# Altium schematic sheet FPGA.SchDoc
size A0
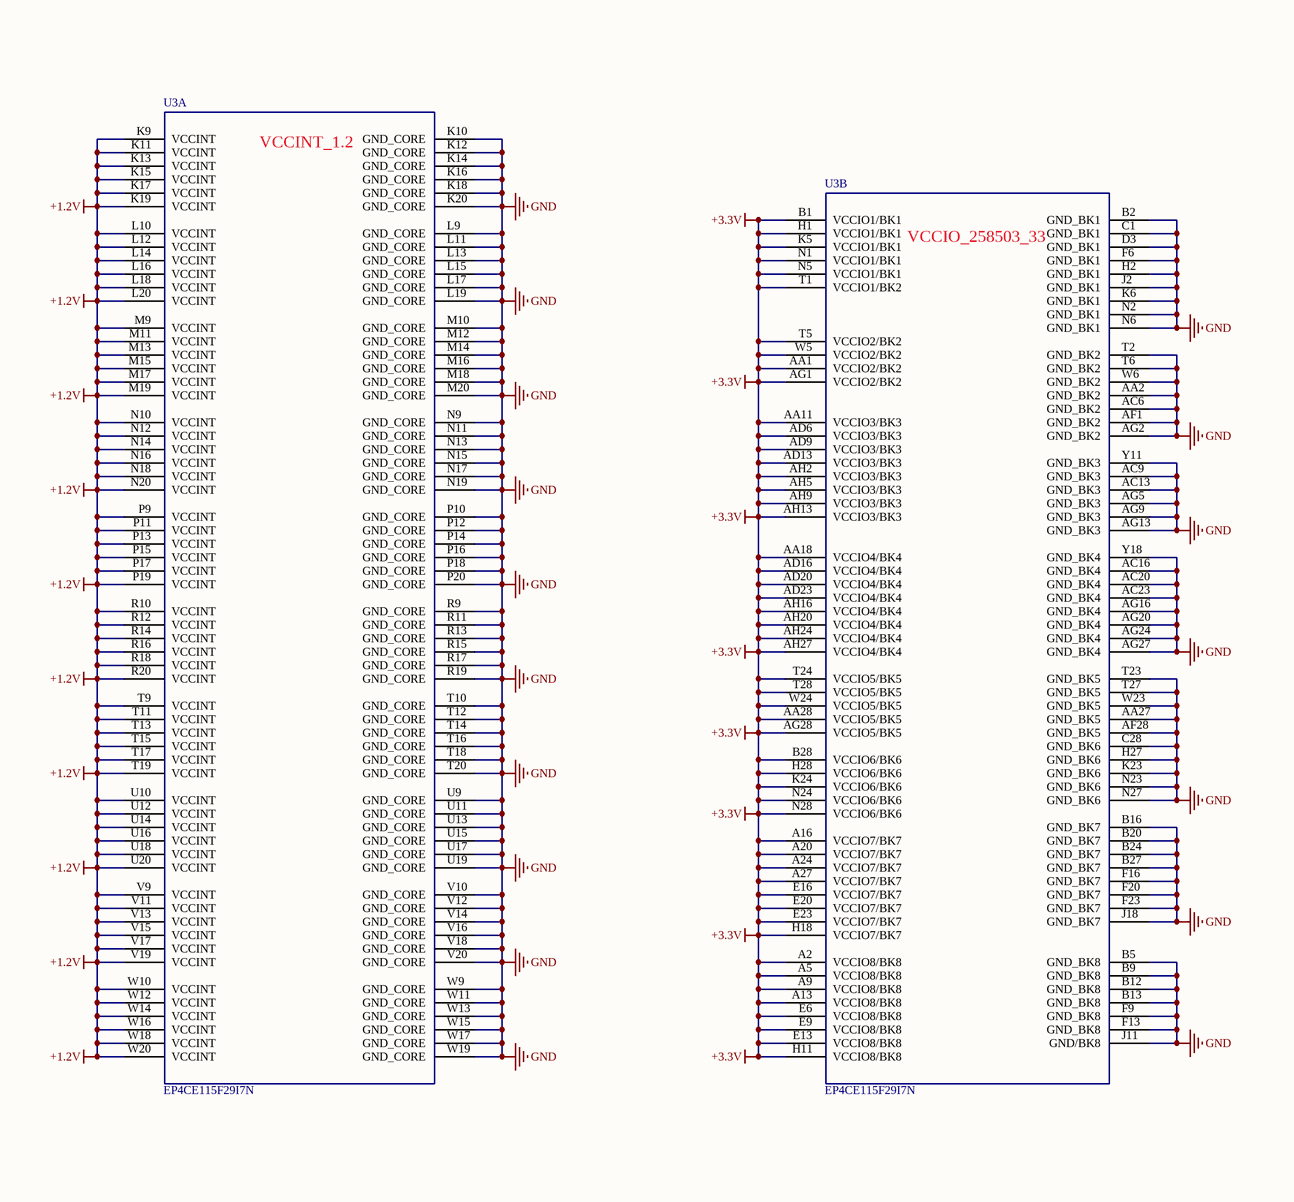
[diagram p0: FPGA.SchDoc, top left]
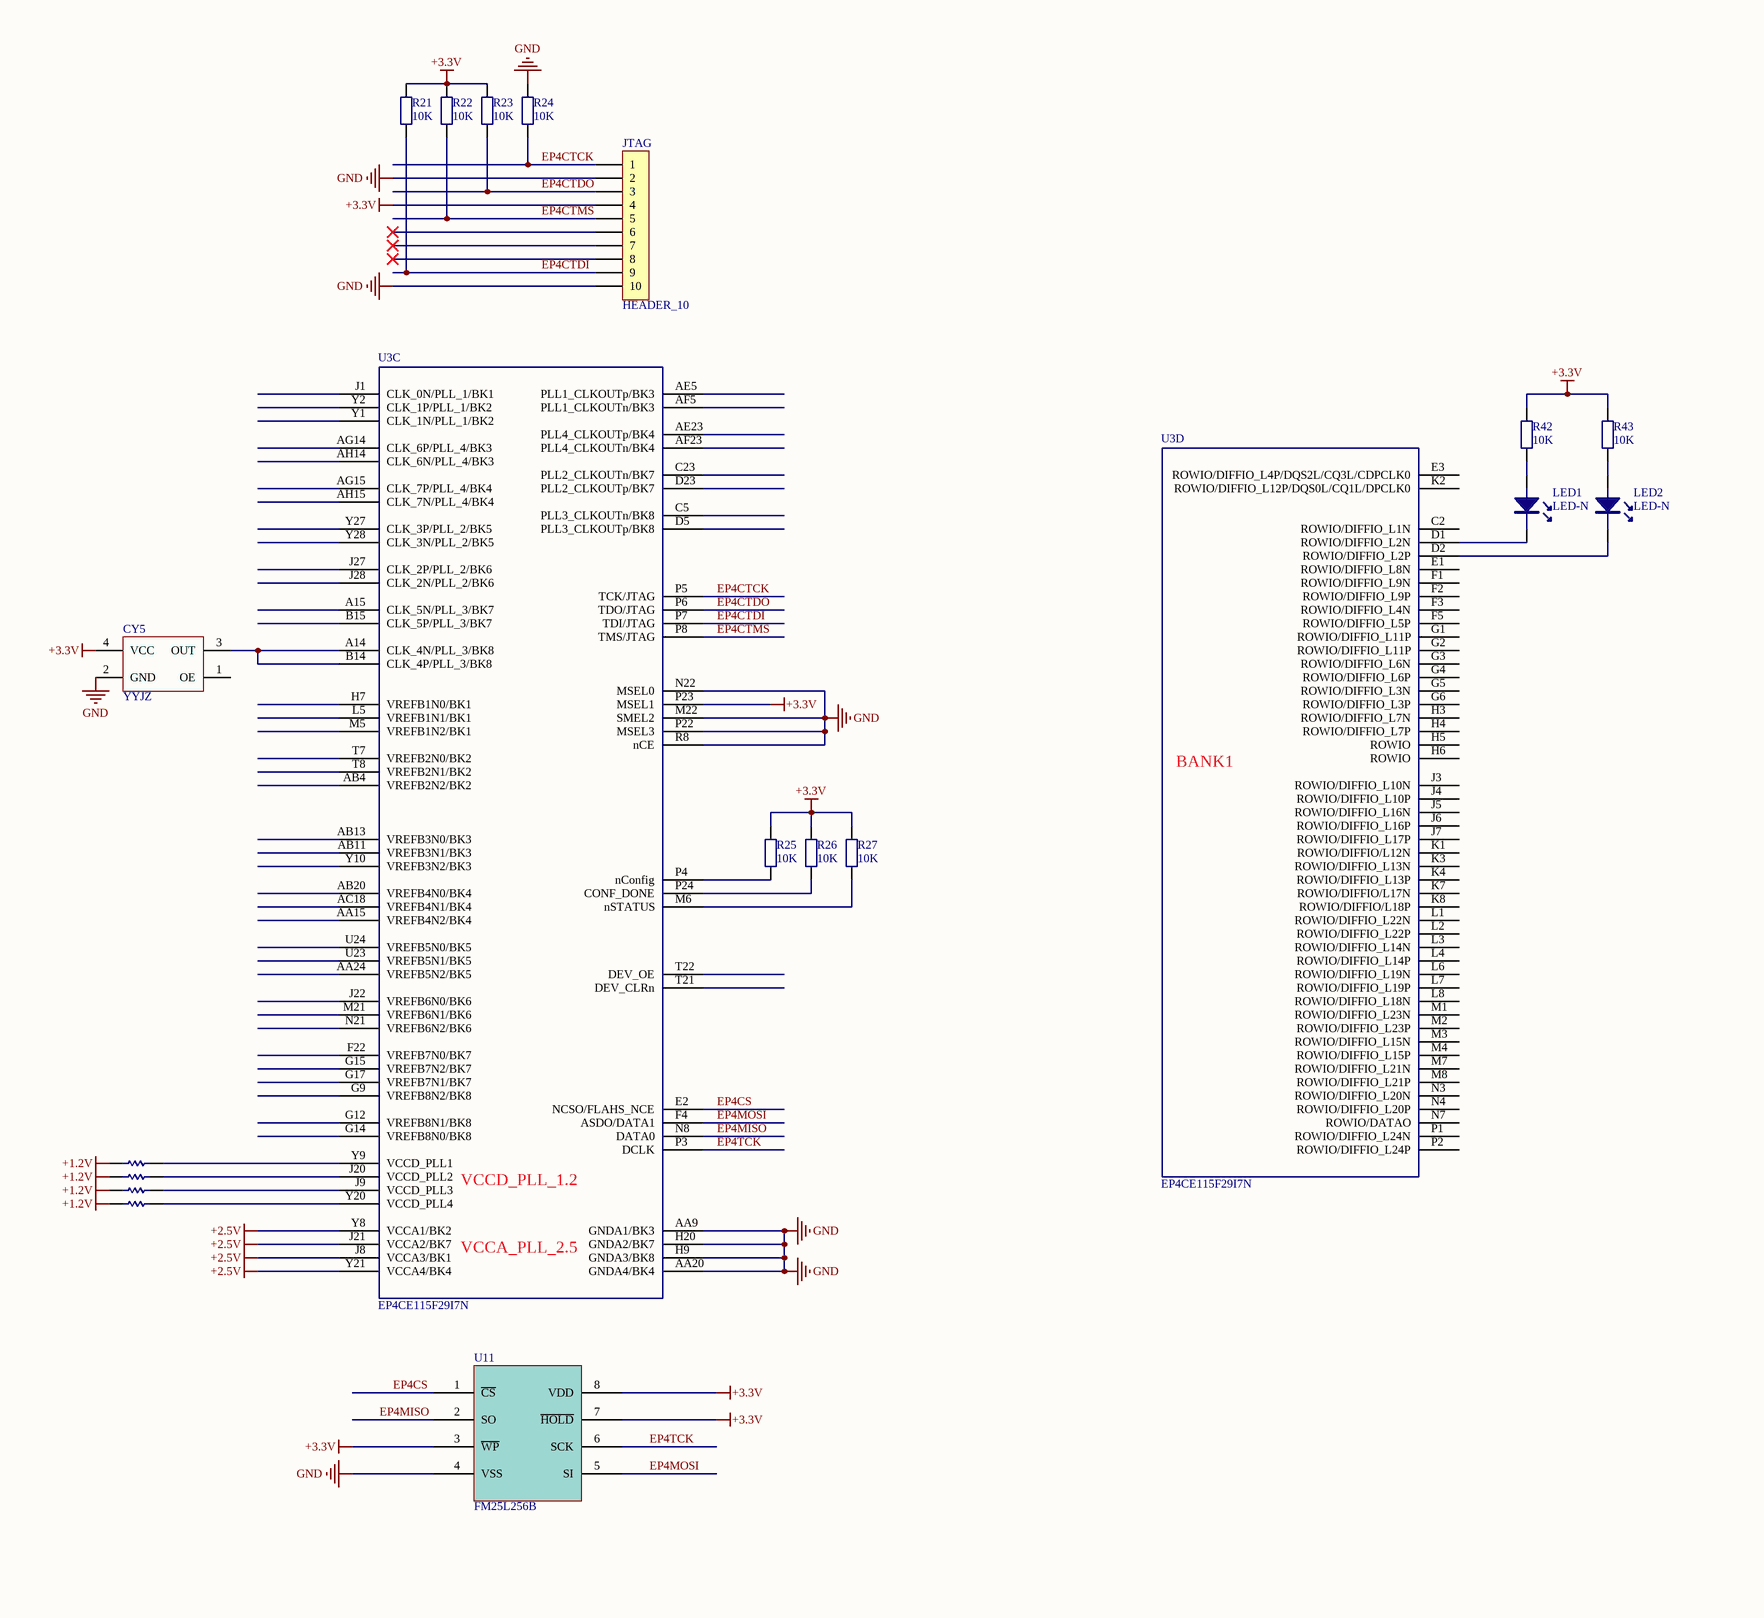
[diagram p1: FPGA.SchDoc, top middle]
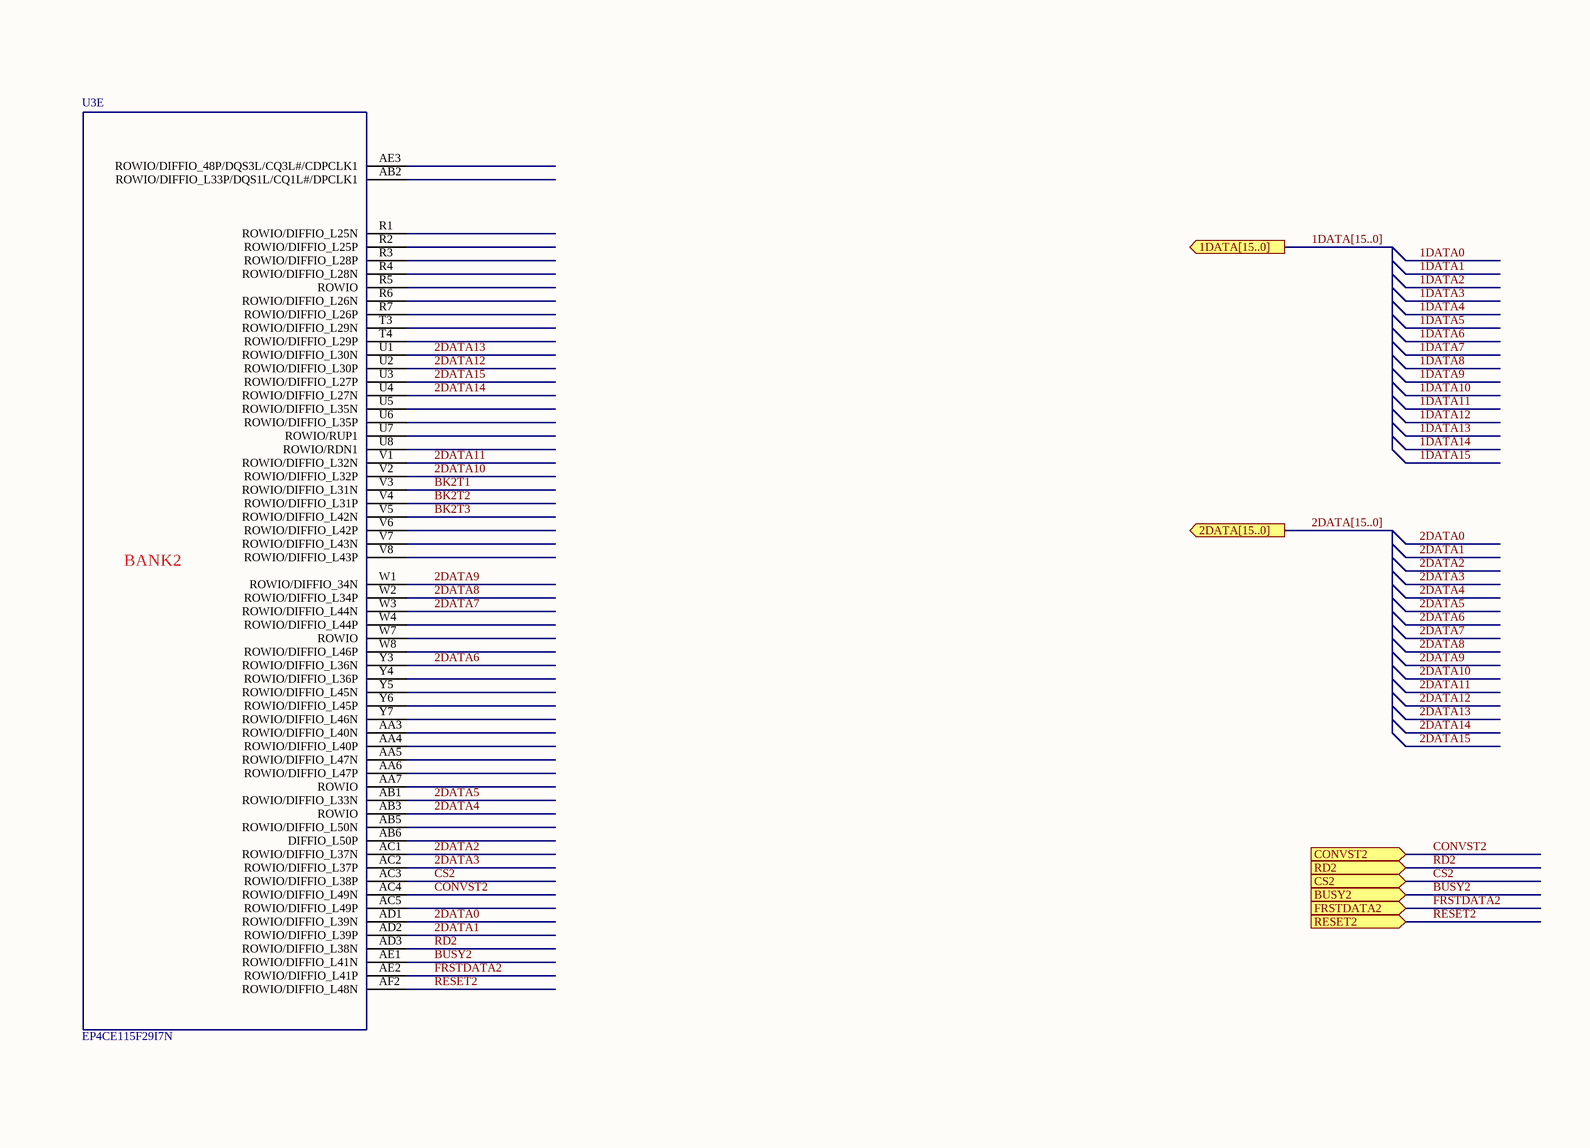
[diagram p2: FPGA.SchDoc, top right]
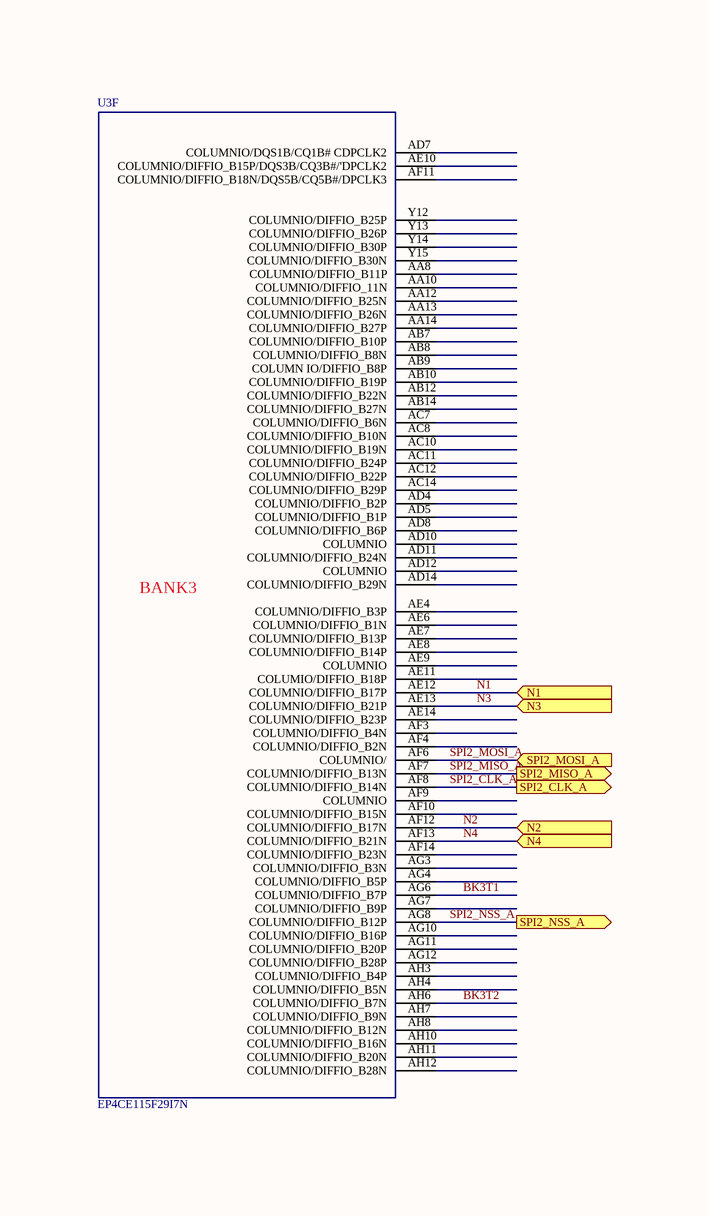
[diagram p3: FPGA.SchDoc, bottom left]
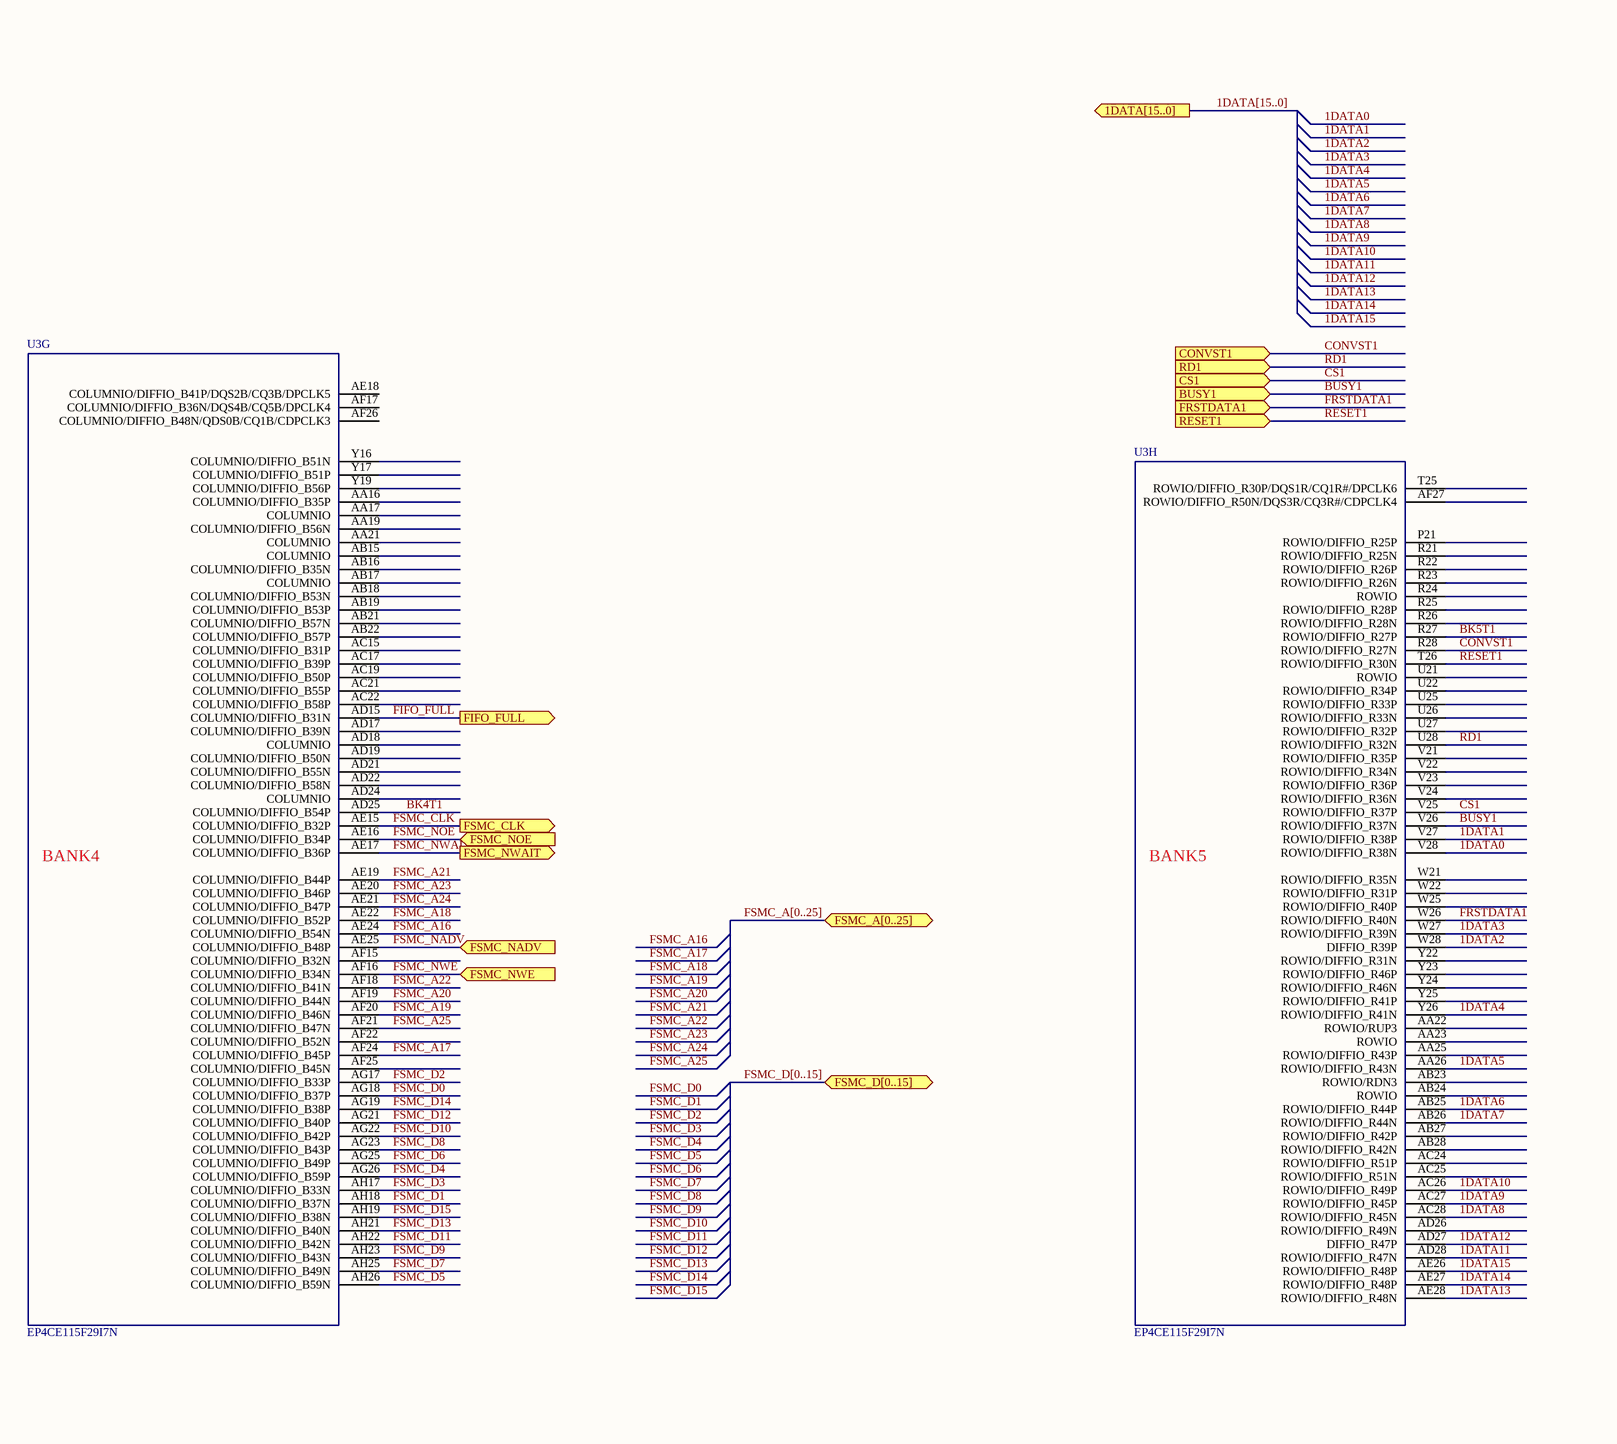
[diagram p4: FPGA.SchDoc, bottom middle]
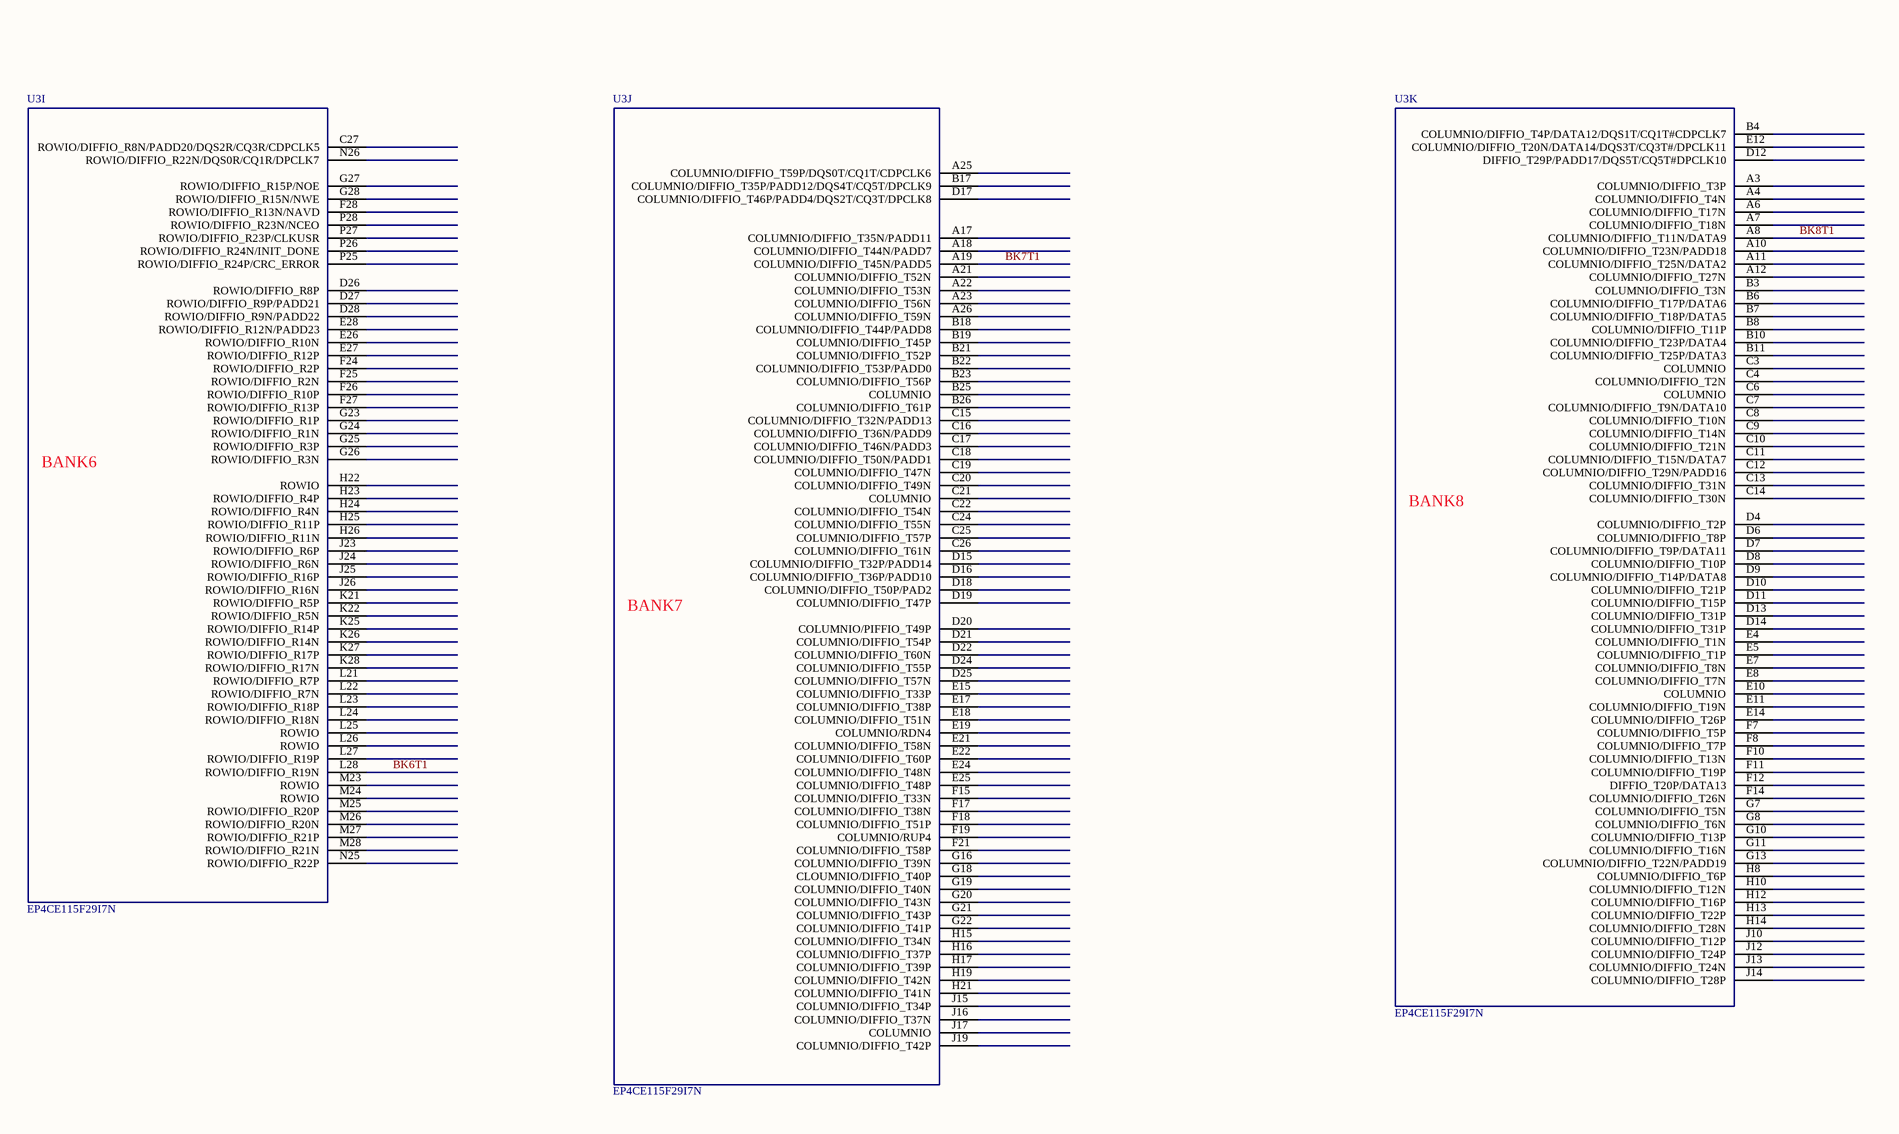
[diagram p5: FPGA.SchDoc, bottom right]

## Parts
CY5  YYJZ  [YYJZ]
CZ2  CZ  [CZ]  (value not drawn)
CZ3  CZ  [CZ]  (value not drawn)
CZ4  CZ  [CZ]  (value not drawn)
CZ5  CZ  [CZ]  (value not drawn)
JTAG  HEADER_10  [JTAG]
LED1  LED-N  [0805_LED]
LED2  LED-N  [0805_LED]
R21  10K  [R0805]
R22  10K  [R0805]
R23  10K  [R0805]
R24  10K  [R0805]
R25  10K  [R0603]
R26  10K  [R0603]
R27  10K  [R0603]
R42  10K  [R0805]
R43  10K  [R0805]
U3  EP4CE115F29I7N  [FBGA780]  (parts A,B,C,D,E,F,G,H,I,J,K of 11)
U11  FM25L256B  [SOIC8]

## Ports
1DATA[15..0] (out), 2DATA[15..0] (out), BUSY1 (in), BUSY2 (in), CONVST1 (in), CONVST2 (in), CS1 (in), CS2 (in), FIFO_FULL (out), FRSTDATA1 (in), FRSTDATA2 (in), FSMC_A[0..25] (bidir), FSMC_CLK (out), FSMC_D[0..15] (bidir), FSMC_NADV (in), FSMC_NOE (in), FSMC_NWAIT (out), FSMC_NWE (in), N1 (in), N2 (in), N3 (in), N4 (in), RD1 (in), RD2 (in), RESET1 (in), RESET2 (in), SPI2_CLK_A (out), SPI2_MISO_A (out), SPI2_MOSI_A (in), SPI2_NSS_A (out)

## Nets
+1.2V: CZ2.1 CZ3.1 CZ4.2 CZ5.2 U3.K9(VCCINT) U3.K11(VCCINT) U3.K13(VCCINT) U3.K15(VCCINT) U3.K17(VCCINT) U3.K19(VCCINT) U3.L10(VCCINT) U3.L12(VCCINT) U3.L14(VCCINT) U3.L16(VCCINT) U3.L18(VCCINT) U3.L20(VCCINT) U3.M9(VCCINT) U3.M11(VCCINT) U3.M13(VCCINT) U3.M15(VCCINT) U3.M17(VCCINT) U3.M19(VCCINT) U3.N10(VCCINT) U3.N12(VCCINT) U3.N14(VCCINT) U3.N16(VCCINT) U3.N18(VCCINT) U3.N20(VCCINT) U3.P9(VCCINT) U3.P11(VCCINT) U3.P13(VCCINT) U3.P15(VCCINT) U3.P17(VCCINT) U3.P19(VCCINT) U3.R10(VCCINT) U3.R12(VCCINT) U3.R14(VCCINT) U3.R16(VCCINT) U3.R18(VCCINT) U3.R20(VCCINT) U3.T9(VCCINT) U3.T11(VCCINT) U3.T13(VCCINT) U3.T15(VCCINT) U3.T17(VCCINT) U3.T19(VCCINT) U3.U10(VCCINT) U3.U12(VCCINT) U3.U14(VCCINT) U3.U16(VCCINT) U3.U18(VCCINT) U3.U20(VCCINT) U3.V9(VCCINT) U3.V11(VCCINT) U3.V13(VCCINT) U3.V15(VCCINT) U3.V17(VCCINT) U3.V19(VCCINT) U3.W10(VCCINT) U3.W12(VCCINT) U3.W14(VCCINT) U3.W16(VCCINT) U3.W18(VCCINT) U3.W20(VCCINT)
+2.5V: U3.J8(VCCA3/BK1) U3.J21(VCCA2/BK7) U3.Y8(VCCA1/BK2) U3.Y21(VCCA4/BK4)
+3.3V: CY5.4(VCC) JTAG.4 R21.2 R22.2 R23.2 R25.2 R26.2 R27.2 R42.2 R43.2 U3.A2(VCCIO8/BK8) U3.A5(VCCIO8/BK8) U3.A9(VCCIO8/BK8) U3.A13(VCCIO8/BK8) U3.A16(VCCIO7/BK7) U3.A20(VCCIO7/BK7) U3.A24(VCCIO7/BK7) U3.A27(VCCIO7/BK7) U3.AA1(VCCIO2/BK2) U3.AA11(VCCIO3/BK3) U3.AA18(VCCIO4/BK4) U3.AA28(VCCIO5/BK5) U3.AD6(VCCIO3/BK3) U3.AD9(VCCIO3/BK3) U3.AD13(VCCIO3/BK3) U3.AD16(VCCIO4/BK4) U3.AD20(VCCIO4/BK4) U3.AD23(VCCIO4/BK4) U3.AG1(VCCIO2/BK2) U3.AG28(VCCIO5/BK5) U3.AH2(VCCIO3/BK3) U3.AH5(VCCIO3/BK3) U3.AH9(VCCIO3/BK3) U3.AH13(VCCIO3/BK3) U3.AH16(VCCIO4/BK4) U3.AH20(VCCIO4/BK4) U3.AH24(VCCIO4/BK4) U3.AH27(VCCIO4/BK4) U3.B1(VCCIO1/BK1) U3.B28(VCCIO6/BK6) U3.E6(VCCIO8/BK8) U3.E9(VCCIO8/BK8) U3.E13(VCCIO8/BK8) U3.E16(VCCIO7/BK7) U3.E20(VCCIO7/BK7) U3.E23(VCCIO7/BK7) U3.H1(VCCIO1/BK1) U3.H11(VCCIO8/BK8) U3.H18(VCCIO7/BK7) U3.H28(VCCIO6/BK6) U3.K5(VCCIO1/BK1) U3.K24(VCCIO6/BK6) U3.N1(VCCIO1/BK1) U3.N5(VCCIO1/BK1) U3.N24(VCCIO6/BK6) U3.N28(VCCIO6/BK6) U3.P23(MSEL1) U3.T1(VCCIO1/BK2) U3.T5(VCCIO2/BK2) U3.T24(VCCIO5/BK5) U3.T28(VCCIO5/BK5) U3.W5(VCCIO2/BK2) U3.W24(VCCIO5/BK5) U11.3(~{WP}) U11.7(~{HOLD}) U11.8(VDD)
GND: CY5.2(GND) JTAG.2 JTAG.10 R24.2 U3.AA2(GND_BK2) U3.AA9(GNDA1/BK3) U3.AA20(GNDA4/BK4) U3.AA27(GND_BK5) U3.AC6(GND_BK2) U3.AC9(GND_BK3) U3.AC13(GND_BK3) U3.AC16(GND_BK4) U3.AC20(GND_BK4) U3.AC23(GND_BK4) U3.AF1(GND_BK2) U3.AF28(GND_BK5) U3.AG2(GND_BK2) U3.AG5(GND_BK3) U3.AG9(GND_BK3) U3.AG13(GND_BK3) U3.AG16(GND_BK4) U3.AG20(GND_BK4) U3.AG24(GND_BK4) U3.AG27(GND_BK4) U3.B2(GND_BK1) U3.B5(GND_BK8) U3.B9(GND_BK8) U3.B12(GND_BK8) U3.B13(GND_BK8) U3.B16(GND_BK7) U3.B20(GND_BK7) U3.B24(GND_BK7) U3.B27(GND_BK7) U3.C1(GND_BK1) U3.C28(GND_BK6) U3.D3(GND_BK1) U3.F6(GND_BK1) U3.F9(GND_BK8) U3.F13(GND_BK8) U3.F16(GND_BK7) U3.F20(GND_BK7) U3.F23(GND_BK7) U3.H2(GND_BK1) U3.H9(GNDA3/BK8) U3.H20(GNDA2/BK7) U3.H27(GND_BK6) U3.J2(GND_BK1) U3.J11(GND/BK8) U3.J18(GND_BK7) U3.K6(GND_BK1) U3.K10(GND_CORE) U3.K12(GND_CORE) U3.K14(GND_CORE) U3.K16(GND_CORE) U3.K18(GND_CORE) U3.K20(GND_CORE) U3.K23(GND_BK6) U3.L9(GND_CORE) U3.L11(GND_CORE) U3.L13(GND_CORE) U3.L15(GND_CORE) U3.L17(GND_CORE) U3.L19(GND_CORE) U3.M10(GND_CORE) U3.M12(GND_CORE) U3.M14(GND_CORE) U3.M16(GND_CORE) U3.M18(GND_CORE) U3.M20(GND_CORE) U3.M22(SMEL2) U3.N2(GND_BK1) U3.N6(GND_BK1) U3.N9(GND_CORE) U3.N11(GND_CORE) U3.N13(GND_CORE) U3.N15(GND_CORE) U3.N17(GND_CORE) U3.N19(GND_CORE) U3.N22(MSEL0) U3.N23(GND_BK6) U3.N27(GND_BK6) U3.P10(GND_CORE) U3.P12(GND_CORE) U3.P14(GND_CORE) U3.P16(GND_CORE) U3.P18(GND_CORE) U3.P20(GND_CORE) U3.P22(MSEL3) U3.R8(nCE) U3.R9(GND_CORE) U3.R11(GND_CORE) U3.R13(GND_CORE) U3.R15(GND_CORE) U3.R17(GND_CORE) U3.R19(GND_CORE) U3.T2(GND_BK2) U3.T6(GND_BK2) U3.T10(GND_CORE) U3.T12(GND_CORE) U3.T14(GND_CORE) U3.T16(GND_CORE) U3.T18(GND_CORE) U3.T20(GND_CORE) U3.T23(GND_BK5) U3.T27(GND_BK5) U3.U9(GND_CORE) U3.U11(GND_CORE) U3.U13(GND_CORE) U3.U15(GND_CORE) U3.U17(GND_CORE) U3.U19(GND_CORE) U3.V10(GND_CORE) U3.V12(GND_CORE) U3.V14(GND_CORE) U3.V16(GND_CORE) U3.V18(GND_CORE) U3.V20(GND_CORE) U3.W6(GND_BK2) U3.W9(GND_CORE) U3.W11(GND_CORE) U3.W13(GND_CORE) U3.W15(GND_CORE) U3.W17(GND_CORE) U3.W19(GND_CORE) U3.W23(GND_BK5) U3.Y11(GND_BK3) U3.Y18(GND_BK4) U11.4(VSS)
1DATA0: U3.V28(ROWIO/DIFFIO_R38N)
1DATA1: U3.V27(ROWIO/DIFFIO_R38P)
1DATA2: U3.W28(DIFFIO_R39P)
1DATA3: U3.W27(ROWIO/DIFFIO_R39N)
1DATA4: U3.Y26(ROWIO/DIFFIO_R41N)
1DATA5: U3.AA26(ROWIO/DIFFIO_R43N)
1DATA6: U3.AB25(ROWIO/DIFFIO_R44P)
1DATA7: U3.AB26(ROWIO/DIFFIO_R44N)
1DATA8: U3.AC28(ROWIO/DIFFIO_R45N)
1DATA9: U3.AC27(ROWIO/DIFFIO_R45P)
1DATA10: U3.AC26(ROWIO/DIFFIO_R49P)
1DATA11: U3.AD28(ROWIO/DIFFIO_R47N)
1DATA12: U3.AD27(DIFFIO_R47P)
1DATA13: U3.AE28(ROWIO/DIFFIO_R48N)
1DATA14: U3.AE27(ROWIO/DIFFIO_R48P)
1DATA15: U3.AE26(ROWIO/DIFFIO_R48P)
2DATA0: U3.AD1(ROWIO/DIFFIO_L39N)
2DATA1: U3.AD2(ROWIO/DIFFIO_L39P)
2DATA2: U3.AC1(ROWIO/DIFFIO_L37N)
2DATA3: U3.AC2(ROWIO/DIFFIO_L37P)
2DATA4: U3.AB3(ROWIO)
2DATA5: U3.AB1(ROWIO/DIFFIO_L33N)
2DATA6: U3.Y3(ROWIO/DIFFIO_L36N)
2DATA7: U3.W3(ROWIO/DIFFIO_L44N)
2DATA8: U3.W2(ROWIO/DIFFIO_L34P)
2DATA9: U3.W1(ROWIO/DIFFIO_34N)
2DATA10: U3.V2(ROWIO/DIFFIO_L32P)
2DATA11: U3.V1(ROWIO/DIFFIO_L32N)
2DATA12: U3.U2(ROWIO/DIFFIO_L30P)
2DATA13: U3.U1(ROWIO/DIFFIO_L30N)
2DATA14: U3.U4(ROWIO/DIFFIO_L27N)
2DATA15: U3.U3(ROWIO/DIFFIO_L27P)
BK2T1: U3.V3(ROWIO/DIFFIO_L31N)
BK2T2: U3.V4(ROWIO/DIFFIO_L31P)
BK2T3: U3.V5(ROWIO/DIFFIO_L42N)
BK3T1: U3.AG6(COLUMNIO/DIFFIO_B7P)
BK3T2: U3.AH6(COLUMNIO/DIFFIO_B7N)
BK4T1: U3.AD25(COLUMNIO/DIFFIO_B54P)
BK5T1: U3.R27(ROWIO/DIFFIO_R27P)
BK6T1: U3.L28(ROWIO/DIFFIO_R19N)
BK7T1: U3.A19(COLUMNIO/DIFFIO_T45N/PADD5)
BK8T1: U3.A8(COLUMNIO/DIFFIO_T11N/DATA9)
BUSY1: U3.V26(ROWIO/DIFFIO_R37N) ; port BUSY1
BUSY2: U3.AE1(ROWIO/DIFFIO_L41N) ; port BUSY2
CONVST1: U3.R28(ROWIO/DIFFIO_R27N) ; port CONVST1
CONVST2: U3.AC4(ROWIO/DIFFIO_L49N) ; port CONVST2
CS1: U3.V25(ROWIO/DIFFIO_R37P) ; port CS1
CS2: U3.AC3(ROWIO/DIFFIO_L38P) ; port CS2
EP4CS: U3.E2(NCSO/FLAHS_NCE) U11.1(~{CS})
EP4CTCK: JTAG.1 R24.1 U3.P5(TCK/JTAG)
EP4CTDI: JTAG.9 R21.1 U3.P7(TDI/JTAG)
EP4CTDO: JTAG.3 R23.1 U3.P6(TDO/JTAG)
EP4CTMS: JTAG.5 R22.1 U3.P8(TMS/JTAG)
EP4MISO: U3.N8(DATA0) U11.2(SO)
EP4MOSI: U3.F4(ASDO/DATA1) U11.5(SI)
EP4TCK: U3.P3(DCLK) U11.6(SCK)
FIFO_FULL: U3.AD15(COLUMNIO/DIFFIO_B31N) ; port FIFO_FULL
FRSTDATA1: U3.W26(ROWIO/DIFFIO_R40N) ; port FRSTDATA1
FRSTDATA2: U3.AE2(ROWIO/DIFFIO_L41P) ; port FRSTDATA2
FSMC_A16: U3.AE24(COLUMNIO/DIFFIO_B54N)
FSMC_A17: U3.AF24(COLUMNIO/DIFFIO_B45P)
FSMC_A18: U3.AE22(COLUMNIO/DIFFIO_B52P)
FSMC_A19: U3.AF20(COLUMNIO/DIFFIO_B46N)
FSMC_A20: U3.AF19(COLUMNIO/DIFFIO_B44N)
FSMC_A21: U3.AE19(COLUMNIO/DIFFIO_B44P)
FSMC_A22: U3.AF18(COLUMNIO/DIFFIO_B41N)
FSMC_A23: U3.AE20(COLUMNIO/DIFFIO_B46P)
FSMC_A24: U3.AE21(COLUMNIO/DIFFIO_B47P)
FSMC_A25: U3.AF21(COLUMNIO/DIFFIO_B47N)
FSMC_CLK: U3.AE15(COLUMNIO/DIFFIO_B32P) ; port FSMC_CLK
FSMC_D0: U3.AG18(COLUMNIO/DIFFIO_B37P)
FSMC_D1: U3.AH18(COLUMNIO/DIFFIO_B37N)
FSMC_D2: U3.AG17(COLUMNIO/DIFFIO_B33P)
FSMC_D3: U3.AH17(COLUMNIO/DIFFIO_B33N)
FSMC_D4: U3.AG26(COLUMNIO/DIFFIO_B59P)
FSMC_D5: U3.AH26(COLUMNIO/DIFFIO_B59N)
FSMC_D6: U3.AG25(COLUMNIO/DIFFIO_B49P)
FSMC_D7: U3.AH25(COLUMNIO/DIFFIO_B49N)
FSMC_D8: U3.AG23(COLUMNIO/DIFFIO_B43P)
FSMC_D9: U3.AH23(COLUMNIO/DIFFIO_B43N)
FSMC_D10: U3.AG22(COLUMNIO/DIFFIO_B42P)
FSMC_D11: U3.AH22(COLUMNIO/DIFFIO_B42N)
FSMC_D12: U3.AG21(COLUMNIO/DIFFIO_B40P)
FSMC_D13: U3.AH21(COLUMNIO/DIFFIO_B40N)
FSMC_D14: U3.AG19(COLUMNIO/DIFFIO_B38P)
FSMC_D15: U3.AH19(COLUMNIO/DIFFIO_B38N)
FSMC_NADV: U3.AE25(COLUMNIO/DIFFIO_B48P) ; port FSMC_NADV
FSMC_NOE: U3.AE16(COLUMNIO/DIFFIO_B34P) ; port FSMC_NOE
FSMC_NWAIT: U3.AE17(COLUMNIO/DIFFIO_B36P) ; port FSMC_NWAIT
FSMC_NWE: U3.AF16(COLUMNIO/DIFFIO_B34N) ; port FSMC_NWE
N1: U3.AE12(COLUMNIO/DIFFIO_B17P) ; port N1
N2: U3.AF12(COLUMNIO/DIFFIO_B17N) ; port N2
N3: U3.AE13(COLUMNIO/DIFFIO_B21P) ; port N3
N4: U3.AF13(COLUMNIO/DIFFIO_B21N) ; port N4
RD1: U3.U28(ROWIO/DIFFIO_R32N) ; port RD1
RD2: U3.AD3(ROWIO/DIFFIO_L38N) ; port RD2
RESET1: U3.T26(ROWIO/DIFFIO_R30N) ; port RESET1
RESET2: U3.AF2(ROWIO/DIFFIO_L48N) ; port RESET2
SPI2_CLK_A: U3.AF8(COLUMNIO/DIFFIO_B14N) ; port SPI2_CLK_A
SPI2_MISO_A: U3.AF7(COLUMNIO/DIFFIO_B13N) ; port SPI2_MISO_A
SPI2_MOSI_A: U3.AF6(COLUMNIO/) ; port SPI2_MOSI_A
SPI2_NSS_A: U3.AG8(COLUMNIO/DIFFIO_B12P) ; port SPI2_NSS_A
NetCY5_3: CY5.3(OUT) U3.A14(CLK_4N/PLL_3/BK8) U3.B14(CLK_4P/PLL_3/BK8)
NetCZ2_2: CZ2.2 U3.Y9(VCCD_PLL1)
NetCZ3_2: CZ3.2 U3.J20(VCCD_PLL2)
NetCZ4_1: CZ4.1 U3.J9(VCCD_PLL3)
NetCZ5_1: CZ5.1 U3.Y20(VCCD_PLL4)
NetLED1_1: LED1.1 R42.1
NetLED1_2: LED1.2 U3.D1(ROWIO/DIFFIO_L2N)
NetLED2_1: LED2.1 R43.1
NetLED2_2: LED2.2 U3.D2(ROWIO/DIFFIO_L2P)
NetR25_1: R25.1 U3.P4(nConfig)
NetR26_1: R26.1 U3.P24(CONF_DONE)
NetR27_1: R27.1 U3.M6(nSTATUS)

Not connected (* = marked no-connect by the designer): CY5 1(OE); JTAG 6* 7* 8*; U3 A3(COLUMNIO/DIFFIO_T3P) A4(COLUMNIO/DIFFIO_T4N) A6(COLUMNIO/DIFFIO_T17N) A7(COLUMNIO/DIFFIO_T18N) A10(COLUMNIO/DIFFIO_T23N/PADD18) A11(COLUMNIO/DIFFIO_T25N/DATA2) A12(COLUMNIO/DIFFIO_T27N) A15(CLK_5N/PLL_3/BK7) A17(COLUMNIO/DIFFIO_T35N/PADD11) A18(COLUMNIO/DIFFIO_T44N/PADD7) A21(COLUMNIO/DIFFIO_T52N) A22(COLUMNIO/DIFFIO_T53N) A23(COLUMNIO/DIFFIO_T56N) A25(COLUMNIO/DIFFIO_T59P/DQS0T/CQ1T/CDPCLK6) A26(COLUMNIO/DIFFIO_T59N) AA3(ROWIO/DIFFIO_L40N) AA4(ROWIO/DIFFIO_L40P) AA5(ROWIO/DIFFIO_L47N) AA6(ROWIO/DIFFIO_L47P) AA7(ROWIO) AA8(COLUMNIO/DIFFIO_B11P) AA10(COLUMNIO/DIFFIO_11N) AA12(COLUMNIO/DIFFIO_B25N) AA13(COLUMNIO/DIFFIO_B26N) AA14(COLUMNIO/DIFFIO_B27P) AA15(VREFB4N2/BK4) AA16(COLUMNIO/DIFFIO_B35P) AA17(COLUMNIO) AA19(COLUMNIO/DIFFIO_B56N) AA21(COLUMNIO) AA22(ROWIO/RUP3) AA23(ROWIO) AA24(VREFB5N2/BK5) AA25(ROWIO/DIFFIO_R43P) AB2(ROWIO/DIFFIO_L33P/DQS1L/CQ1L#/DPCLK1) AB4(VREFB2N2/BK2) AB5(ROWIO/DIFFIO_L50N) AB6(DIFFIO_L50P) AB7(COLUMNIO/DIFFIO_B10P) AB8(COLUMNIO/DIFFIO_B8N) AB9(COLUMN_IO/DIFFIO_B8P) AB10(COLUMNIO/DIFFIO_B19P) AB11(VREFB3N1/BK3) AB12(COLUMNIO/DIFFIO_B22N) AB13(VREFB3N0/BK3) AB14(COLUMNIO/DIFFIO_B27N) AB15(COLUMNIO) AB16(COLUMNIO/DIFFIO_B35N) AB17(COLUMNIO) AB18(COLUMNIO/DIFFIO_B53N) AB19(COLUMNIO/DIFFIO_B53P) AB20(VREFB4N0/BK4) AB21(COLUMNIO/DIFFIO_B57N) AB22(COLUMNIO/DIFFIO_B57P) AB23(ROWIO/RDN3) AB24(ROWIO) AB27(ROWIO/DIFFIO_R42P) AB28(ROWIO/DIFFIO_R42N) AC5(ROWIO/DIFFIO_L49P) AC7(COLUMNIO/DIFFIO_B6N) AC8(COLUMNIO/DIFFIO_B10N) AC10(COLUMNIO/DIFFIO_B19N) AC11(COLUMNIO/DIFFIO_B24P) AC12(COLUMNIO/DIFFIO_B22P) AC14(COLUMNIO/DIFFIO_B29P) AC15(COLUMNIO/DIFFIO_B31P) AC17(COLUMNIO/DIFFIO_B39P) AC18(VREFB4N1/BK4) AC19(COLUMNIO/DIFFIO_B50P) AC21(COLUMNIO/DIFFIO_B55P) AC22(COLUMNIO/DIFFIO_B58P) AC24(ROWIO/DIFFIO_R51P) AC25(ROWIO/DIFFIO_R51N) AD4(COLUMNIO/DIFFIO_B2P) AD5(COLUMNIO/DIFFIO_B1P) AD7(COLUMNIO/DQS1B/CQ1B#_CDPCLK2) AD8(COLUMNIO/DIFFIO_B6P) AD10(COLUMNIO) AD11(COLUMNIO/DIFFIO_B24N) AD12(COLUMNIO) AD14(COLUMNIO/DIFFIO_B29N) AD17(COLUMNIO/DIFFIO_B39N) AD18(COLUMNIO) AD19(COLUMNIO/DIFFIO_B50N) AD21(COLUMNIO/DIFFIO_B55N) AD22(COLUMNIO/DIFFIO_B58N) AD24(COLUMNIO) AD26(ROWIO/DIFFIO_R49N) AE3(ROWIO/DIFFIO_48P/DQS3L/CQ3L#/CDPCLK1) AE4(COLUMNIO/DIFFIO_B3P) AE5(PLL1_CLKOUTp/BK3) AE6(COLUMNIO/DIFFIO_B1N) AE7(COLUMNIO/DIFFIO_B13P) AE8(COLUMNIO/DIFFIO_B14P) AE9(COLUMNIO) AE10(COLUMNIO/DIFFIO_B15P/DQS3B/CQ3B#/'DPCLK2) AE11(COLUMIO/DIFFIO_B18P) AE14(COLUMNIO/DIFFIO_B23P) AE18(COLUMNIO/DIFFIO_B41P/DQS2B/CQ3B/DPCLK5) AE23(PLL4_CLKOUTp/BK4) AF3(COLUMNIO/DIFFIO_B4N) AF4(COLUMNIO/DIFFIO_B2N) AF5(PLL1_CLKOUTn/BK3) AF9(COLUMNIO) AF10(COLUMNIO/DIFFIO_B15N) AF11(COLUMNIO/DIFFIO_B18N/DQS5B/CQ5B#/DPCLK3) AF14(COLUMNIO/DIFFIO_B23N) AF15(COLUMNIO/DIFFIO_B32N) AF17(COLUMNIO/DIFFIO_B36N/DQS4B/CQ5B/DPCLK4) AF22(COLUMNIO/DIFFIO_B52N) AF23(PLL4_CLKOUTn/BK4) AF25(COLUMNIO/DIFFIO_B45N) AF26(COLUMNIO/DIFFIO_B48N/QDS0B/CQ1B/CDPCLK3) AF27(ROWIO/DIFFIO_R50N/DQS3R/CQ3R#/CDPCLK4) AG3(COLUMNIO/DIFFIO_B3N) AG4(COLUMNIO/DIFFIO_B5P) AG7(COLUMNIO/DIFFIO_B9P) AG10(COLUMNIO/DIFFIO_B16P) AG11(COLUMNIO/DIFFIO_B20P) AG12(COLUMNIO/DIFFIO_B28P) AG14(CLK_6P/PLL_4/BK3) AG15(CLK_7P/PLL_4/BK4) AH3(COLUMNIO/DIFFIO_B4P) AH4(COLUMNIO/DIFFIO_B5N) AH7(COLUMNIO/DIFFIO_B9N) AH8(COLUMNIO/DIFFIO_B12N) AH10(COLUMNIO/DIFFIO_B16N) AH11(COLUMNIO/DIFFIO_B20N) AH12(COLUMNIO/DIFFIO_B28N) AH14(CLK_6N/PLL_4/BK3) AH15(CLK_7N/PLL_4/BK4) B3(COLUMNIO/DIFFIO_T3N) B4(COLUMNIO/DIFFIO_T4P/DATA12/DQS1T/CQ1T#CDPCLK7) B6(COLUMNIO/DIFFIO_T17P/DATA6) B7(COLUMNIO/DIFFIO_T18P/DATA5) B8(COLUMNIO/DIFFIO_T11P) B10(COLUMNIO/DIFFIO_T23P/DATA4) B11(COLUMNIO/DIFFIO_T25P/DATA3) B15(CLK_5P/PLL_3/BK7) B17(COLUMNIO/DIFFIO_T35P/PADD12/DQS4T/CQ5T/DPCLK9) B18(COLUMNIO/DIFFIO_T44P/PADD8) B19(COLUMNIO/DIFFIO_T45P) B21(COLUMNIO/DIFFIO_T52P) B22(COLUMNIO/DIFFIO_T53P/PADD0) B23(COLUMNIO/DIFFIO_T56P) B25(COLUMNIO) B26(COLUMNIO/DIFFIO_T61P) C2(ROWIO/DIFFIO_L1N) C3(COLUMNIO) C4(COLUMNIO/DIFFIO_T2N) C5(PLL3_CLKOUTn/BK8) C6(COLUMNIO) C7(COLUMNIO/DIFFIO_T9N/DATA10) C8(COLUMNIO/DIFFIO_T10N) C9(COLUMNIO/DIFFIO_T14N) C10(COLUMNIO/DIFFIO_T21N) C11(COLUMNIO/DIFFIO_T15N/DATA7) C12(COLUMNIO/DIFFIO_T29N/PADD16) C13(COLUMNIO/DIFFIO_T31N) C14(COLUMNIO/DIFFIO_T30N) C15(COLUMNIO/DIFFIO_T32N/PADD13) C16(COLUMNIO/DIFFIO_T36N/PADD9) C17(COLUMNIO/DIFFIO_T46N/PADD3) C18(COLUMNIO/DIFFIO_T50N/PADD1) C19(COLUMNIO/DIFFIO_T47N) C20(COLUMNIO/DIFFIO_T49N) C21(COLUMNIO) C22(COLUMNIO/DIFFIO_T54N) C23(PLL2_CLKOUTn/BK7) C24(COLUMNIO/DIFFIO_T55N) C25(COLUMNIO/DIFFIO_T57P) C26(COLUMNIO/DIFFIO_T61N) C27(ROWIO/DIFFIO_R8N/PADD20/DQS2R/CQ3R/CDPCLK5) D4(COLUMNIO/DIFFIO_T2P) D5(PLL3_CLKOUTp/BK8) D6(COLUMNIO/DIFFIO_T8P) D7(COLUMNIO/DIFFIO_T9P/DATA11) D8(COLUMNIO/DIFFIO_T10P) D9(COLUMNIO/DIFFIO_T14P/DATA8) D10(COLUMNIO/DIFFIO_T21P) D11(COLUMNIO/DIFFIO_T15P) D12(DIFFIO_T29P/PADD17/DQS5T/CQ5T#DPCLK10) D13(COLUMNIO/DIFFIO_T31P) D14(COLUMNIO/DIFFIO_T31P) D15(COLUMNIO/DIFFIO_T32P/PADD14) D16(COLUMNIO/DIFFIO_T36P/PADD10) D17(COLUMNIO/DIFFIO_T46P/PADD4/DQS2T/CQ3T/DPCLK8) D18(COLUMNIO/DIFFIO_T50P/PAD2) D19(COLUMNIO/DIFFIO_T47P) D20(COLUMNIO/PIFFIO_T49P) D21(COLUMNIO/DIFFIO_T54P) D22(COLUMNIO/DIFFIO_T60N) D23(PLL2_CLKOUTp/BK7) D24(COLUMNIO/DIFFIO_T55P) D25(COLUMNIO/DIFFIO_T57N) D26(ROWIO/DIFFIO_R8P) D27(ROWIO/DIFFIO_R9P/PADD21) D28(ROWIO/DIFFIO_R9N/PADD22) E1(ROWIO/DIFFIO_L8N) E3(ROWIO/DIFFIO_L4P/DQS2L/CQ3L/CDPCLK0) E4(COLUMNIO/DIFFIO_T1N) E5(COLUMNIO/DIFFIO_T1P) E7(COLUMNIO/DIFFIO_T8N) E8(COLUMNIO/DIFFIO_T7N) E10(COLUMNIO) E11(COLUMNIO/DIFFIO_T19N) E12(COLUMNIO/DIFFIO_T20N/DATA14/DQS3T/CQ3T#/DPCLK11) E14(COLUMNIO/DIFFIO_T26P) E15(COLUMNIO/DIFFIO_T33P) E17(COLUMNIO/DIFFIO_T38P) E18(COLUMNIO/DIFFIO_T51N) E19(COLUMNIO/RDN4) E21(COLUMNIO/DIFFIO_T58N) E22(COLUMNIO/DIFFIO_T60P) E24(COLUMNIO/DIFFIO_T48N) E25(COLUMNIO/DIFFIO_T48P) E26(ROWIO/DIFFIO_R10N) E27(ROWIO/DIFFIO_R12P) E28(ROWIO/DIFFIO_R12N/PADD23) F1(ROWIO/DIFFIO_L9N) F2(ROWIO/DIFFIO_L9P) F3(ROWIO/DIFFIO_L4N) F5(ROWIO/DIFFIO_L5P) F7(COLUMNIO/DIFFIO_T5P) F8(COLUMNIO/DIFFIO_T7P) F10(COLUMNIO/DIFFIO_T13N) F11(COLUMNIO/DIFFIO_T19P) F12(DIFFIO_T20P/DATA13) F14(COLUMNIO/DIFFIO_T26N) F15(COLUMNIO/DIFFIO_T33N) F17(COLUMNIO/DIFFIO_T38N) F18(COLUMNIO/DIFFIO_T51P) F19(COLUMNIO/RUP4) F21(COLUMNIO/DIFFIO_T58P) F22(VREFB7N0/BK7) F24(ROWIO/DIFFIO_R2P) F25(ROWIO/DIFFIO_R2N) F26(ROWIO/DIFFIO_R10P) F27(ROWIO/DIFFIO_R13P) F28(ROWIO/DIFFIO_R13N/NAVD) G1(ROWIO/DIFFIO_L11P) G2(ROWIO/DIFFIO_L11P) G3(ROWIO/DIFFIO_L6N) G4(ROWIO/DIFFIO_L6P) G5(ROWIO/DIFFIO_L3N) G6(ROWIO/DIFFIO_L3P) G7(COLUMNIO/DIFFIO_T5N) G8(COLUMNIO/DIFFIO_T6N) G9(VREFB8N2/BK8) G10(COLUMNIO/DIFFIO_T13P) G11(COLUMNIO/DIFFIO_T16N) G12(VREFB8N1/BK8) G13(COLUMNIO/DIFFIO_T22N/PADD19) G14(VREFB8N0/BK8) G15(VREFB7N2/BK7) G16(COLUMNIO/DIFFIO_T39N) G17(VREFB7N1/BK7) G18(CLOUMNIO/DIFFIO_T40P) G19(COLUMNIO/DIFFIO_T40N) G20(COLUMNIO/DIFFIO_T43N) G21(COLUMNIO/DIFFIO_T43P) G22(COLUMNIO/DIFFIO_T41P) G23(ROWIO/DIFFIO_R1P) G24(ROWIO/DIFFIO_R1N) G25(ROWIO/DIFFIO_R3P) G26(ROWIO/DIFFIO_R3N) G27(ROWIO/DIFFIO_R15P/NOE) G28(ROWIO/DIFFIO_R15N/NWE) H3(ROWIO/DIFFIO_L7N) H4(ROWIO/DIFFIO_L7P) H5(ROWIO) H6(ROWIO) H7(VREFB1N0/BK1) H8(COLUMNIO/DIFFIO_T6P) H10(COLUMNIO/DIFFIO_T12N) H12(COLUMNIO/DIFFIO_T16P) H13(COLUMNIO/DIFFIO_T22P) H14(COLUMNIO/DIFFIO_T28N) H15(COLUMNIO/DIFFIO_T34N) H16(COLUMNIO/DIFFIO_T37P) H17(COLUMNIO/DIFFIO_T39P) H19(COLUMNIO/DIFFIO_T42N) H21(COLUMNIO/DIFFIO_T41N) H22(ROWIO) H23(ROWIO/DIFFIO_R4P) H24(ROWIO/DIFFIO_R4N) H25(ROWIO/DIFFIO_R11P) H26(ROWIO/DIFFIO_R11N) J1(CLK_0N/PLL_1/BK1) J3(ROWIO/DIFFIO_L10N) J4(ROWIO/DIFFIO_L10P) J5(ROWIO/DIFFIO_L16N) J6(ROWIO/DIFFIO_L16P) J7(ROWIO/DIFFIO_L17P) J10(COLUMNIO/DIFFIO_T12P) J12(COLUMNIO/DIFFIO_T24P) J13(COLUMNIO/DIFFIO_T24N) J14(COLUMNIO/DIFFIO_T28P) J15(COLUMNIO/DIFFIO_T34P) J16(COLUMNIO/DIFFIO_T37N) J17(COLUMNIO) J19(COLUMNIO/DIFFIO_T42P) J22(VREFB6N0/BK6) J23(ROWIO/DIFFIO_R6P) J24(ROWIO/DIFFIO_R6N) J25(ROWIO/DIFFIO_R16P) J26(ROWIO/DIFFIO_R16N) J27(CLK_2P/PLL_2/BK6) J28(CLK_2N/PLL_2/BK6) K1(ROWIO/DIFFIO/L12N) K2(ROWIO/DIFFIO_L12P/DQS0L/CQ1L/DPCLK0) K3(ROWIO/DIFFIO_L13N) K4(ROWIO/DIFFIO_L13P) K7(ROWIO/DIFFIO/L17N) K8(ROWIO/DIFFIO/L18P) K21(ROWIO/DIFFIO_R5P) K22(ROWIO/DIFFIO_R5N) K25(ROWIO/DIFFIO_R14P) K26(ROWIO/DIFFIO_R14N) K27(ROWIO/DIFFIO_R17P) K28(ROWIO/DIFFIO_R17N) L1(ROWIO/DIFFIO_L22N) L2(ROWIO/DIFFIO_L22P) L3(ROWIO/DIFFIO_L14N) L4(ROWIO/DIFFIO_L14P) L5(VREFB1N1/BK1) L6(ROWIO/DIFFIO_L19N) L7(ROWIO/DIFFIO_L19P) L8(ROWIO/DIFFIO_L18N) L21(ROWIO/DIFFIO_R7P) L22(ROWIO/DIFFIO_R7N) L23(ROWIO/DIFFIO_R18P) L24(ROWIO/DIFFIO_R18N) L25(ROWIO) L26(ROWIO) L27(ROWIO/DIFFIO_R19P) M1(ROWIO/DIFFIO_L23N) M2(ROWIO/DIFFIO_L23P) M3(ROWIO/DIFFIO_L15N) M4(ROWIO/DIFFIO_L15P) M5(VREFB1N2/BK1) M7(ROWIO/DIFFIO_L21N) M8(ROWIO/DIFFIO_L21P) M21(VREFB6N1/BK6) M23(ROWIO) M24(ROWIO) M25(ROWIO/DIFFIO_R20P) M26(ROWIO/DIFFIO_R20N) M27(ROWIO/DIFFIO_R21P) M28(ROWIO/DIFFIO_R21N) N3(ROWIO/DIFFIO_L20N) N4(ROWIO/DIFFIO_L20P) N7(ROWIO/DATAO) N21(VREFB6N2/BK6) N25(ROWIO/DIFFIO_R22P) N26(ROWIO/DIFFIO_R22N/DQS0R/CQ1R/DPCLK7) P1(ROWIO/DIFFIO_L24N) P2(ROWIO/DIFFIO_L24P) P21(ROWIO/DIFFIO_R25P) P25(ROWIO/DIFFIO_R24P/CRC_ERROR) P26(ROWIO/DIFFIO_R24N/INIT_DONE) P27(ROWIO/DIFFIO_R23P/CLKUSR) P28(ROWIO/DIFFIO_R23N/NCEO) R1(ROWIO/DIFFIO_L25N) R2(ROWIO/DIFFIO_L25P) R3(ROWIO/DIFFIO_L28P) R4(ROWIO/DIFFIO_L28N) R5(ROWIO) R6(ROWIO/DIFFIO_L26N) R7(ROWIO/DIFFIO_L26P) R21(ROWIO/DIFFIO_R25N) R22(ROWIO/DIFFIO_R26P) R23(ROWIO/DIFFIO_R26N) R24(ROWIO) R25(ROWIO/DIFFIO_R28P) R26(ROWIO/DIFFIO_R28N) T3(ROWIO/DIFFIO_L29N) T4(ROWIO/DIFFIO_L29P) T7(VREFB2N0/BK2) T8(VREFB2N1/BK2) T21(DEV_CLRn) T22(DEV_OE) T25(ROWIO/DIFFIO_R30P/DQS1R/CQ1R#/DPCLK6) U5(ROWIO/DIFFIO_L35N) U6(ROWIO/DIFFIO_L35P) U7(ROWIO/RUP1) U8(ROWIO/RDN1) U21(ROWIO) U22(ROWIO/DIFFIO_R34P) U23(VREFB5N1/BK5) U24(VREFB5N0/BK5) U25(ROWIO/DIFFIO_R33P) U26(ROWIO/DIFFIO_R33N) U27(ROWIO/DIFFIO_R32P) V6(ROWIO/DIFFIO_L42P) V7(ROWIO/DIFFIO_L43N) V8(ROWIO/DIFFIO_L43P) V21(ROWIO/DIFFIO_R35P) V22(ROWIO/DIFFIO_R34N) V23(ROWIO/DIFFIO_R36P) V24(ROWIO/DIFFIO_R36N) W4(ROWIO/DIFFIO_L44P) W7(ROWIO) W8(ROWIO/DIFFIO_L46P) W21(ROWIO/DIFFIO_R35N) W22(ROWIO/DIFFIO_R31P) W25(ROWIO/DIFFIO_R40P) Y1(CLK_1N/PLL_1/BK2) Y2(CLK_1P/PLL_1/BK2) Y4(ROWIO/DIFFIO_L36P) Y5(ROWIO/DIFFIO_L45N) Y6(ROWIO/DIFFIO_L45P) Y7(ROWIO/DIFFIO_L46N) Y10(VREFB3N2/BK3) Y12(COLUMNIO/DIFFIO_B25P) Y13(COLUMNIO/DIFFIO_B26P) Y14(COLUMNIO/DIFFIO_B30P) Y15(COLUMNIO/DIFFIO_B30N) Y16(COLUMNIO/DIFFIO_B51N) Y17(COLUMNIO/DIFFIO_B51P) Y19(COLUMNIO/DIFFIO_B56P) Y22(ROWIO/DIFFIO_R31N) Y23(ROWIO/DIFFIO_R46P) Y24(ROWIO/DIFFIO_R46N) Y25(ROWIO/DIFFIO_R41P) Y27(CLK_3P/PLL_2/BK5) Y28(CLK_3N/PLL_2/BK5)

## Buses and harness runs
bus 1DATA[15..0] = port 1DATA[15..0]
bus 2DATA[15..0] = port 2DATA[15..0]
bus FSMC_A[0..25] = port FSMC_A[0..25]
bus FSMC_D[0..15] = port FSMC_D[0..15]

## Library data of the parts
R21-R27 R42 R43 = RES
